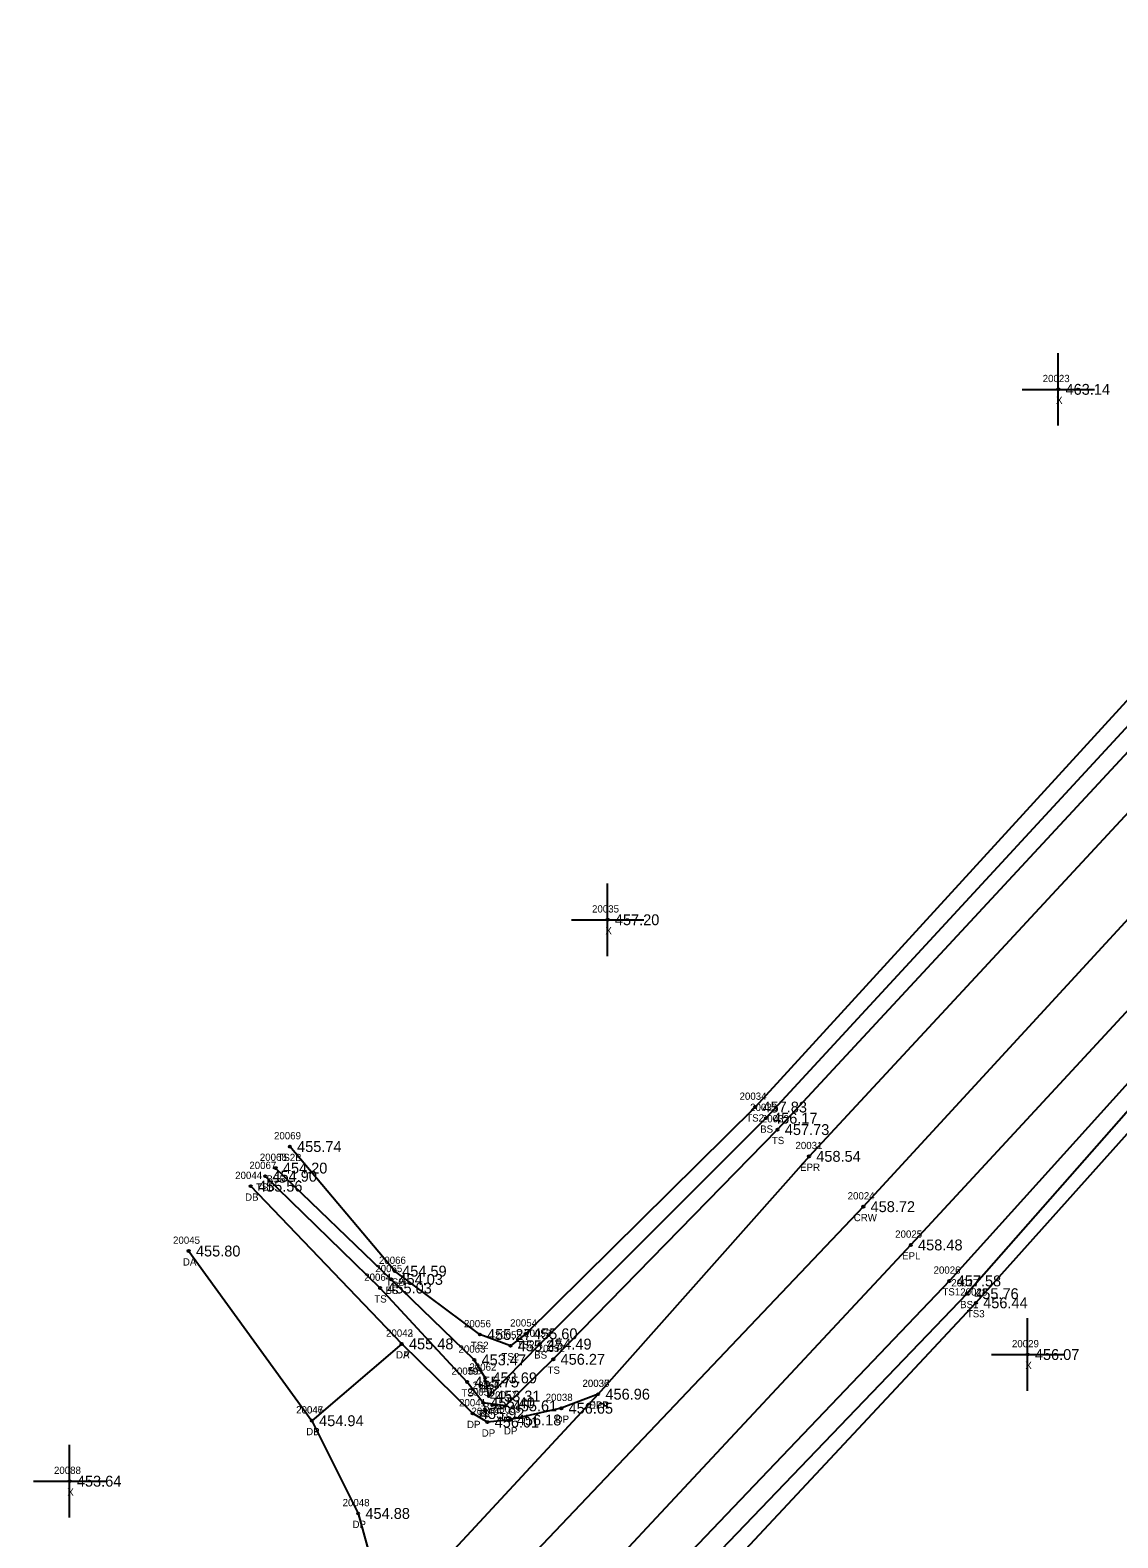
# Model space of a CAD drawing. Extents: x 1763022 to 1764007, y 824123 to 825394.
# Drawn here: x 1763705.9 to 1763855.9, y 825164.8 to 825372.8 of the extents above; entities that cross this region are included whole.
import ezdxf

# ---------------------------------------------------------------- set-up
doc = ezdxf.new("R2010")
doc.units = 0
for name, color, linetype in [('RD_DTM_BkLn1', 7, 'Continuous'), ('RD_DTM_BkLn2', 7, 'Continuous'), ('RD_DTM_BkLn_txCode', 7, 'Continuous'), ('RD_EX_Driveway', 7, 'Continuous'), ('RD_EX_Driveway_txCode', 7, 'Continuous'), ('RD_EX_Misc', 7, 'Continuous'), ('RD_EX_Misc_txCode', 7, 'Continuous'), ('RD_EX_Road', 7, 'Continuous'), ('RD_EX_Road_txCode', 7, 'Continuous'), ('RD_EX_TX_Driveway_ELEV', 7, 'Continuous'), ('RD_EX_TX_Misc_ELEV', 7, 'Continuous'), ('RD_EX_TX_Road_ELEV', 7, 'Continuous'), ('RD_HC_Survey_ELEV', 7, 'Continuous'), ('RD_HC_Survey_txCode', 7, 'Continuous'), ('RD_SMD_Locator', 7, 'Continuous')]:
    doc.layers.add(name, color=color, linetype=linetype)

msp = doc.modelspace()

# ---------------------------------------------------------------- linework, layer by layer
at = {"layer": 'RD_DTM_BkLn1'}
msp.add_lwpolyline([(1763957.85, 825358.99), (1763889.22, 825284.86), (1763820.79, 825210.5), (1763751.37, 825137.44), (1763682.52, 825063.34), (1763613.99, 824989.62), (1763581.46, 824952.08), (1763550.2, 824912.66), (1763519.29, 824872.78), (1763491.16, 824832.15)], dxfattribs=at)
at = {"layer": 'RD_DTM_BkLn2'}
for points in [[(1763942.94, 825372.76), (1763874.29, 825299), (1763805.88, 825224.24), (1763774.23, 825192.97), (1763772.12, 825191.31), (1763767.89, 825192.87), (1763756.18, 825201.61), (1763741.69, 825218.79)], [(1763945.44, 825370.55), (1763876.18, 825297.25), (1763807.34, 825222.7), (1763776.17, 825191.55), (1763769.13, 825184.38), (1763768.64, 825186.89), (1763767.13, 825189.37), (1763755.67, 825200.47), (1763739.73, 825215.82)], [(1763947.84, 825368.13), (1763877.96, 825295.52), (1763808.96, 825221.13), (1763778.03, 825189.45), (1763771.43, 825183.03), (1763768.35, 825183.44), (1763766.15, 825186.32), (1763754.14, 825199.28), (1763738.29, 825214.7)], [(1763968.07, 825349.7), (1763900.27, 825275.17), (1763832.66, 825200.26), (1763762.42, 825126.65), (1763692.83, 825054.38), (1763655.96, 825013.92), (1763657.67, 825011.86), (1763660.66, 825010.25)], [(1763969.49, 825348.41), (1763901.67, 825274.17), (1763835.08, 825198.5), (1763765.09, 825125.58), (1763695.51, 825052.15), (1763658.81, 825013.59)], [(1763971.84, 825347.08), (1763903.21, 825271.94), (1763836.32, 825197.24), (1763767.44, 825123.48), (1763698.39, 825048.89), (1763660.66, 825010.25)]]:
    msp.add_lwpolyline(points, dxfattribs=at)
at = {"layer": 'RD_EX_Driveway'}
for p, q in [((1763757.12, 825191.57), (1763736.3, 825213.32)), ((1763727.74, 825204.38), (1763744.73, 825180.98))]:
    msp.add_line(p, q, dxfattribs=at)
msp.add_lwpolyline([(1763784.22, 825184.64), (1763779.13, 825182.7), (1763772, 825181.08), (1763768.94, 825180.79), (1763766.91, 825181.97), (1763757.12, 825191.57), (1763744.73, 825180.98), (1763751.12, 825168.19), (1763753.07, 825160.99), (1763754.38, 825152.48)], dxfattribs=at)
at = {"layer": 'RD_EX_Misc'}
for p, q in [((1763847.68, 825318.22), (1763847.68, 825328.22)), ((1763842.68, 825323.22), (1763852.68, 825323.22)), ((1763785.52, 825245.07), (1763785.52, 825255.07)), ((1763780.52, 825250.07), (1763790.52, 825250.07)), ((1763843.45, 825185.11), (1763843.45, 825195.11)), ((1763838.45, 825190.11), (1763848.45, 825190.11)), ((1763711.32, 825167.64), (1763711.32, 825177.64)), ((1763706.32, 825172.64), (1763716.32, 825172.64))]:
    msp.add_line(p, q, dxfattribs=at)
at = {"layer": 'RD_EX_Road'}
for points in [[(1763951.03, 825365.44), (1763882.12, 825291.59), (1763813.3, 825217.44), (1763784.22, 825184.64), (1763754.38, 825152.48), (1763744.67, 825142.84), (1763675.27, 825070.17), (1763607.46, 824995.53), (1763574.27, 824958.09), (1763542.37, 824919.2), (1763512.11, 824877.96), (1763483.2, 824837.35)], [(1763963.89, 825353.59), (1763895.68, 825279.08), (1763827.34, 825205.22), (1763758.38, 825131.33), (1763689.43, 825057.33), (1763653.53, 825018.75), (1763637.74, 825000.8), (1763620.71, 824983.81), (1763588.78, 824946.6), (1763557.13, 824907.38), (1763526.52, 824867.67), (1763498.43, 824827.25)]]:
    msp.add_lwpolyline(points, dxfattribs=at)
at = {"layer": 'RD_SMD_Locator'}
for centre in [(1763847.68, 825323.22), (1763785.52, 825250.07), (1763805.88, 825224.24), (1763807.34, 825222.7), (1763808.96, 825221.13), (1763741.69, 825218.79), (1763813.3, 825217.44), (1763738.29, 825214.7), (1763739.73, 825215.82), (1763736.3, 825213.32), (1763820.79, 825210.5), (1763727.74, 825204.38), (1763827.34, 825205.22), (1763755.67, 825200.47), (1763756.18, 825201.61), (1763832.66, 825200.26), (1763754.14, 825199.28), (1763835.08, 825198.5), (1763836.32, 825197.24), (1763757.12, 825191.57), (1763757.12, 825191.57), (1763767.89, 825192.87), (1763774.23, 825192.97), (1763776.17, 825191.55), (1763767.13, 825189.37), (1763772.12, 825191.31), (1763778.03, 825189.45), (1763843.45, 825190.11), (1763766.15, 825186.32), (1763768.64, 825186.89), (1763768.35, 825183.44), (1763769.13, 825184.38), (1763784.22, 825184.64), (1763784.22, 825184.64), (1763744.73, 825180.98), (1763744.73, 825180.98), (1763766.91, 825181.97), (1763771.43, 825183.03), (1763772, 825181.08), (1763779.13, 825182.7), (1763768.94, 825180.79), (1763711.32, 825172.64), (1763751.12, 825168.19)]:
    msp.add_circle(centre, 0.15, dxfattribs=at)

# ---------------------------------------------------------------- texts
at = {"layer": 'RD_DTM_BkLn_txCode'}
for s, p in [('20034', (1763803.72, 825225.24)), ('TS2', (1763804.64, 825222.24)), ('20033', (1763805.18, 825223.7)), ('20032', (1763806.8, 825222.13)), ('20069', (1763739.51, 825219.79)), ('BS', (1763806.56, 825220.7)), ('TS', (1763808.17, 825219.13)), ('20067', (1763736.11, 825215.7)), ('20068', (1763737.55, 825216.82)), ('TS2B', (1763739.98, 825216.79)), ('BSB', (1763738.47, 825213.82)), ('TSB', (1763737.02, 825212.7)), ('20065', (1763753.48, 825201.47)), ('20066', (1763753.98, 825202.61)), ('20026', (1763830.48, 825201.26)), ('20064', (1763751.95, 825200.28)), ('TS2', (1763754.94, 825199.61)), ('20027', (1763832.93, 825199.5)), ('TS', (1763753.34, 825197.28)), ('BS', (1763754.89, 825198.47)), ('TS1', (1763831.7, 825198.26)), ('20028', (1763834.16, 825198.24)), ('BS1', (1763834.14, 825196.5)), ('TS3', (1763835.07, 825195.24)), ('20056', (1763765.71, 825193.87)), ('20054', (1763772.07, 825193.97)), ('TS2', (1763766.65, 825190.87)), ('20055', (1763769.97, 825192.31)), ('TS2', (1763772.99, 825190.97)), ('20053', (1763774.02, 825192.55)), ('20063', (1763764.95, 825190.37)), ('TS2', (1763770.88, 825189.31)), ('BS', (1763775.39, 825189.55)), ('20052', (1763775.88, 825190.45)), ('20059', (1763763.99, 825187.32)), ('BS', (1763766.35, 825187.37)), ('20062', (1763766.46, 825187.89)), ('TS', (1763777.24, 825187.45)), ('TS', (1763765.35, 825184.32)), ('20058', (1763766.19, 825184.44)), ('20060', (1763766.91, 825185.38)), ('BS', (1763767.86, 825184.89)), ('BS', (1763768.35, 825182.38)), ('20057', (1763769.27, 825184.03)), ('TS', (1763767.55, 825181.44)), ('TS', (1763770.63, 825181.03))]:
    msp.add_text(s, height=1, dxfattribs=at).set_placement(p)
at = {"layer": 'RD_EX_Driveway_txCode'}
for s, p in [('20044', (1763734.15, 825214.32)), ('DB', (1763735.52, 825211.32)), ('20045', (1763725.58, 825205.38)), ('DA', (1763726.94, 825202.38)), ('20042', (1763754.96, 825192.57)), ('20043', (1763754.96, 825192.57)), ('DA', (1763756.33, 825189.57)), ('DP', (1763756.34, 825189.57)), ('20037', (1763782.06, 825185.64)), ('20041', (1763765.03, 825182.97)), ('20038', (1763776.98, 825183.7)), ('DPA', (1763782.95, 825182.64)), ('20046', (1763742.55, 825181.98)), ('20047', (1763742.57, 825181.98)), ('20040', (1763766.74, 825181.79)), ('20039', (1763769.84, 825182.08)), ('DP', (1763778.35, 825180.7)), ('DB', (1763743.95, 825178.98)), ('DP', (1763743.95, 825178.98)), ('DP', (1763766.13, 825179.97)), ('DP', (1763768.16, 825178.79)), ('DP', (1763771.22, 825179.08)), ('20048', (1763748.97, 825169.19)), ('DP', (1763750.34, 825166.19))]:
    msp.add_text(s, height=1, dxfattribs=at).set_placement(p)
at = {"layer": 'RD_EX_Misc_txCode'}
for s, p in [('20023', (1763845.53, 825324.22)), ('X', (1763847.37, 825321.22)), ('20035', (1763783.37, 825251.07)), ('X', (1763785.21, 825248.07)), ('20029', (1763841.29, 825191.11)), ('X', (1763843.13, 825188.11)), ('20088', (1763709.16, 825173.64)), ('X', (1763711, 825170.64))]:
    msp.add_text(s, height=1, dxfattribs=at).set_placement(p)
at = {"layer": 'RD_EX_Road_txCode'}
for s, p in [('20031', (1763811.43, 825218.44)), ('EPR', (1763812.07, 825215.44)), ('20025', (1763825.18, 825206.22)), ('EPL', (1763826.14, 825203.22)), ('20036', (1763782.04, 825185.64)), ('EPR', (1763782.99, 825182.64))]:
    msp.add_text(s, height=1, dxfattribs=at).set_placement(p)
at = {"layer": 'RD_EX_TX_Driveway_ELEV'}
for s, p in [('455.56', (1763737.3, 825212.57)), ('455.80', (1763728.74, 825203.63)), ('455.48', (1763758.12, 825190.82)), ('455.48', (1763758.12, 825190.82)), ('456.96', (1763785.22, 825183.89)), ('456.65', (1763780.13, 825181.95)), ('454.94', (1763745.73, 825180.23)), ('454.94', (1763745.73, 825180.23)), ('455.92', (1763767.91, 825181.22)), ('456.01', (1763769.94, 825180.04)), ('456.18', (1763773, 825180.33)), ('454.88', (1763752.12, 825167.44))]:
    msp.add_text(s, height=1.5, dxfattribs=at).set_placement(p)
at = {"layer": 'RD_EX_TX_Misc_ELEV'}
for s, p in [('463.14', (1763848.68, 825322.47)), ('457.20', (1763786.52, 825249.32)), ('457.83', (1763806.88, 825223.49)), ('456.17', (1763808.34, 825221.95)), ('457.73', (1763809.96, 825220.38)), ('455.74', (1763742.69, 825218.04)), ('454.20', (1763740.73, 825215.07)), ('454.90', (1763739.29, 825213.95)), ('454.59', (1763757.18, 825200.86)), ('455.03', (1763755.14, 825198.53)), ('454.03', (1763756.67, 825199.72)), ('457.58', (1763833.66, 825199.51)), ('455.76', (1763836.08, 825197.75)), ('456.44', (1763837.32, 825196.49)), ('455.27', (1763768.89, 825192.12)), ('455.60', (1763775.23, 825192.22)), ('455.27', (1763773.12, 825190.56)), ('454.49', (1763777.17, 825190.8)), ('453.47', (1763768.13, 825188.62)), ('456.27', (1763779.03, 825188.7)), ('456.07', (1763844.45, 825189.36)), ('453.69', (1763769.64, 825186.14)), ('455.75', (1763767.15, 825185.57)), ('455.40', (1763769.35, 825182.69)), ('453.31', (1763770.13, 825183.63)), ('455.61', (1763772.43, 825182.28)), ('453.64', (1763712.32, 825171.89))]:
    msp.add_text(s, height=1.5, dxfattribs=at).set_placement(p)
at = {"layer": 'RD_EX_TX_Road_ELEV'}
for s, p in [('458.54', (1763814.3, 825216.69)), ('458.48', (1763828.34, 825204.47)), ('456.96', (1763785.22, 825183.89))]:
    msp.add_text(s, height=1.5, dxfattribs=at).set_placement(p)
at = {"layer": 'RD_HC_Survey_ELEV'}
msp.add_text('458.72', height=1.5, dxfattribs=at).set_placement((1763821.79, 825209.75))
at = {"layer": 'RD_HC_Survey_txCode'}
for s, p in [('20024', (1763818.63, 825211.5)), ('CRW', (1763819.47, 825208.5))]:
    msp.add_text(s, height=1, dxfattribs=at).set_placement(p)

doc.saveas('drawing.dxf')
